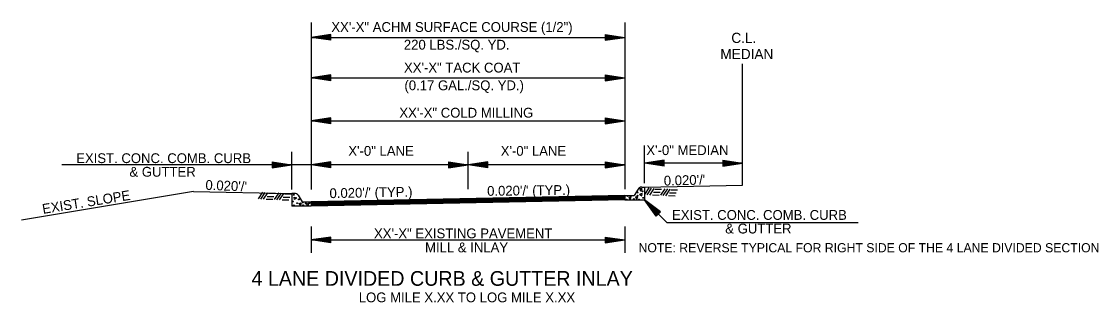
# Model space of a CAD drawing. Extents: x 544199 to 1930787, y -1968972 to 596640.
# Drawn here: x 551627 to 552451, y -1966339 to -1966124 of the extents above; entities that cross this region are included whole.
import ezdxf

# ---------------------------------------------------------------- set-up
doc = ezdxf.new("R2010")
doc.units = 0
doc.layers.add('R_Border Prem', color=7, linetype='Continuous')
doc.layers.add('R_Draft', color=7, linetype='Continuous')

msp = doc.modelspace()

# ---------------------------------------------------------------- linework, layer by layer
at = {"layer": 'R_Draft'}
for p, q in [((551848.34, -1966125.12), (551848.34, -1966252.54)), ((551863.34, -1966134.13), (551848.34, -1966136.38)), ((551848.34, -1966136.38), (552088.27, -1966136.38)), ((551863.34, -1966138.63), (551848.34, -1966136.38)), ((551863.34, -1966134.5), (551850.84, -1966136.38)), ((551863.34, -1966138.25), (551850.84, -1966136.38)), ((551863.34, -1966134.89), (551853.42, -1966136.38)), ((551863.34, -1966137.87), (551853.42, -1966136.38)), ((551863.34, -1966135.26), (551855.92, -1966136.38)), ((551863.34, -1966137.5), (551855.92, -1966136.38)), ((551863.34, -1966135.64), (551858.46, -1966136.38)), ((551863.34, -1966137.11), (551858.46, -1966136.38)), ((551863.34, -1966136.03), (551860.97, -1966136.38)), ((551863.34, -1966136.73), (551860.97, -1966136.38)), ((551863.34, -1966138.63), (551863.34, -1966134.13)), ((552073.27, -1966134.13), (552088.27, -1966136.38)), ((552073.27, -1966134.13), (552073.27, -1966138.63)), ((552073.27, -1966134.5), (552085.76, -1966136.38)), ((552073.27, -1966134.89), (552083.18, -1966136.38)), ((552073.27, -1966135.26), (552080.68, -1966136.38)), ((552073.27, -1966135.65), (552078.14, -1966136.38)), ((552073.27, -1966136.03), (552075.64, -1966136.38)), ((552073.27, -1966138.63), (552088.27, -1966136.38)), ((552073.27, -1966137.11), (552078.14, -1966136.38)), ((552073.27, -1966137.87), (552083.18, -1966136.38)), ((552073.27, -1966138.25), (552085.76, -1966136.38)), ((552073.27, -1966137.5), (552080.68, -1966136.38)), ((552073.27, -1966136.73), (552075.64, -1966136.38)), ((552178.29, -1966249.37), (552178.29, -1966156.59)), ((551863.34, -1966165), (551848.34, -1966167.25)), ((551848.34, -1966167.25), (552088.27, -1966167.25)), ((551863.34, -1966169.5), (551848.34, -1966167.25)), ((551863.34, -1966165.37), (551850.84, -1966167.25)), ((551863.34, -1966169.12), (551850.84, -1966167.25)), ((551863.34, -1966165.76), (551853.42, -1966167.25)), ((551863.34, -1966168.74), (551853.42, -1966167.25)), ((551863.34, -1966166.13), (551855.92, -1966167.25)), ((551863.34, -1966168.37), (551855.92, -1966167.25)), ((551863.34, -1966166.51), (551858.46, -1966167.25)), ((551863.34, -1966167.98), (551858.46, -1966167.25)), ((551863.34, -1966166.9), (551860.97, -1966167.25)), ((551863.34, -1966167.6), (551860.97, -1966167.25)), ((551863.34, -1966169.5), (551863.34, -1966165)), ((552073.27, -1966165), (552088.27, -1966167.25)), ((552073.27, -1966165), (552073.27, -1966169.5)), ((552073.27, -1966165.37), (552085.76, -1966167.25)), ((552073.27, -1966165.76), (552083.18, -1966167.25)), ((552073.27, -1966166.13), (552080.68, -1966167.25)), ((552073.27, -1966166.52), (552078.14, -1966167.25)), ((552073.27, -1966166.9), (552075.64, -1966167.25)), ((552073.27, -1966169.5), (552088.27, -1966167.25)), ((552073.27, -1966167.98), (552078.14, -1966167.25)), ((552073.27, -1966168.74), (552083.18, -1966167.25)), ((552073.27, -1966169.12), (552085.76, -1966167.25)), ((552073.27, -1966168.37), (552080.68, -1966167.25)), ((552073.27, -1966167.6), (552075.64, -1966167.25)), ((551863.34, -1966197.93), (551848.34, -1966200.18)), ((551848.34, -1966200.18), (552088.27, -1966200.18)), ((551863.34, -1966202.43), (551848.34, -1966200.18)), ((551863.34, -1966198.3), (551850.84, -1966200.18)), ((551863.34, -1966202.05), (551850.84, -1966200.18)), ((551863.34, -1966198.68), (551853.42, -1966200.18)), ((551863.34, -1966201.67), (551853.42, -1966200.18)), ((551863.34, -1966199.06), (551855.92, -1966200.18)), ((551863.34, -1966201.29), (551855.92, -1966200.18)), ((551863.34, -1966199.44), (551858.46, -1966200.18)), ((551863.34, -1966200.9), (551858.46, -1966200.18)), ((551863.34, -1966199.82), (551860.97, -1966200.18)), ((551863.34, -1966200.53), (551860.97, -1966200.18)), ((551863.34, -1966202.43), (551863.34, -1966197.93)), ((552073.27, -1966197.93), (552088.27, -1966200.18)), ((552073.27, -1966197.93), (552073.27, -1966202.43)), ((552073.27, -1966198.3), (552085.76, -1966200.18)), ((552073.27, -1966198.68), (552083.18, -1966200.18)), ((552073.27, -1966199.06), (552080.68, -1966200.18)), ((552073.27, -1966199.45), (552078.14, -1966200.18)), ((552073.27, -1966199.82), (552075.64, -1966200.18)), ((552073.27, -1966202.43), (552088.27, -1966200.18)), ((552073.27, -1966200.91), (552078.14, -1966200.18)), ((552073.27, -1966201.67), (552083.18, -1966200.18)), ((552073.27, -1966202.05), (552085.76, -1966200.18)), ((552073.27, -1966201.29), (552080.68, -1966200.18)), ((552073.27, -1966200.53), (552075.64, -1966200.18)), ((552103.27, -1966247.75), (552103.27, -1966219.02)), ((551833.34, -1966252.54), (551833.34, -1966223.82)), ((551968.34, -1966252.37), (551968.34, -1966223.82)), ((551848.34, -1966233.71), (551657.53, -1966233.71)), ((551818.33, -1966231.46), (551833.33, -1966233.71)), ((551818.33, -1966231.46), (551818.33, -1966235.96)), ((551818.33, -1966231.84), (551830.83, -1966233.71)), ((551818.33, -1966232.22), (551828.25, -1966233.71)), ((551818.33, -1966232.6), (551825.75, -1966233.71)), ((551818.33, -1966232.99), (551823.21, -1966233.71)), ((551818.33, -1966233.36), (551820.7, -1966233.71)), ((551818.33, -1966235.96), (551833.33, -1966233.71)), ((551818.33, -1966234.45), (551823.21, -1966233.71)), ((551818.33, -1966235.21), (551828.25, -1966233.71)), ((551818.33, -1966235.59), (551830.83, -1966233.71)), ((551818.33, -1966234.83), (551825.75, -1966233.71)), ((551818.33, -1966234.07), (551820.7, -1966233.71)), ((551863.34, -1966231.46), (551848.34, -1966233.71)), ((551968.34, -1966233.71), (551848.34, -1966233.71)), ((551863.34, -1966235.96), (551848.34, -1966233.71)), ((551863.34, -1966231.84), (551850.84, -1966233.71)), ((551863.34, -1966235.59), (551850.84, -1966233.71)), ((551863.34, -1966232.22), (551853.42, -1966233.71)), ((551863.34, -1966235.21), (551853.42, -1966233.71)), ((551863.34, -1966232.6), (551855.92, -1966233.71)), ((551863.34, -1966234.83), (551855.92, -1966233.71)), ((551863.34, -1966232.98), (551858.46, -1966233.71)), ((551863.34, -1966234.44), (551858.46, -1966233.71)), ((551863.34, -1966233.36), (551860.97, -1966233.71)), ((551863.34, -1966234.07), (551860.97, -1966233.71)), ((551863.34, -1966235.96), (551863.34, -1966231.46)), ((551953.34, -1966231.46), (551968.34, -1966233.71)), ((551953.34, -1966231.46), (551953.34, -1966235.96)), ((551953.34, -1966231.84), (551965.83, -1966233.71)), ((551953.34, -1966232.22), (551963.25, -1966233.71)), ((551953.34, -1966232.6), (551960.76, -1966233.71)), ((551953.34, -1966232.99), (551958.21, -1966233.71)), ((551953.34, -1966233.36), (551955.71, -1966233.71)), ((551953.34, -1966235.96), (551968.34, -1966233.71)), ((551953.34, -1966234.45), (551958.21, -1966233.71)), ((551953.34, -1966235.21), (551963.25, -1966233.71)), ((551953.34, -1966235.59), (551965.83, -1966233.71)), ((551953.34, -1966234.83), (551960.76, -1966233.71)), ((551953.34, -1966234.07), (551955.71, -1966233.71)), ((551983.34, -1966231.46), (551968.34, -1966233.71)), ((552088.27, -1966233.71), (551968.34, -1966233.71)), ((551983.34, -1966235.96), (551968.34, -1966233.71)), ((551983.34, -1966231.84), (551970.84, -1966233.71)), ((551983.34, -1966235.59), (551970.84, -1966233.71)), ((551983.34, -1966232.22), (551973.42, -1966233.71)), ((551983.34, -1966235.21), (551973.42, -1966233.71)), ((551983.34, -1966232.6), (551975.92, -1966233.71)), ((551983.34, -1966234.83), (551975.92, -1966233.71)), ((551983.34, -1966232.98), (551978.46, -1966233.71)), ((551983.34, -1966234.44), (551978.46, -1966233.71)), ((551983.34, -1966233.36), (551980.97, -1966233.71)), ((551983.34, -1966234.07), (551980.97, -1966233.71)), ((551983.34, -1966235.96), (551983.34, -1966231.46)), ((552073.27, -1966231.46), (552088.27, -1966233.71)), ((552073.27, -1966231.46), (552073.27, -1966235.96)), ((552073.27, -1966231.84), (552085.76, -1966233.71)), ((552073.27, -1966232.22), (552083.18, -1966233.71)), ((552073.27, -1966232.6), (552080.68, -1966233.71)), ((552073.27, -1966232.99), (552078.14, -1966233.71)), ((552073.27, -1966233.36), (552075.64, -1966233.71)), ((552073.27, -1966235.96), (552088.27, -1966233.71)), ((552073.27, -1966234.45), (552078.14, -1966233.71)), ((552073.27, -1966235.21), (552083.18, -1966233.71)), ((552073.27, -1966235.59), (552085.76, -1966233.71)), ((552073.27, -1966234.83), (552080.68, -1966233.71)), ((552073.27, -1966234.07), (552075.64, -1966233.71)), ((552118.29, -1966230.23), (552103.29, -1966232.48)), ((552118.29, -1966234.73), (552103.29, -1966232.48)), ((552178.29, -1966232.48), (552103.29, -1966232.48)), ((552118.29, -1966230.61), (552105.8, -1966232.48)), ((552118.29, -1966234.36), (552105.8, -1966232.48)), ((552118.29, -1966230.99), (552108.38, -1966232.48)), ((552118.29, -1966233.97), (552108.38, -1966232.48)), ((552118.29, -1966231.36), (552110.88, -1966232.48)), ((552118.29, -1966233.6), (552110.88, -1966232.48)), ((552118.29, -1966231.75), (552113.42, -1966232.48)), ((552118.29, -1966233.21), (552113.42, -1966232.48)), ((552118.29, -1966232.13), (552115.92, -1966232.48)), ((552118.29, -1966232.83), (552115.92, -1966232.48)), ((552118.29, -1966234.73), (552118.29, -1966230.23)), ((552163.29, -1966230.23), (552178.29, -1966232.48)), ((552163.29, -1966230.23), (552163.29, -1966234.73)), ((552163.29, -1966230.61), (552175.79, -1966232.48)), ((552163.29, -1966230.99), (552173.21, -1966232.48)), ((552163.29, -1966231.36), (552170.71, -1966232.48)), ((552163.29, -1966231.75), (552168.17, -1966232.48)), ((552163.29, -1966232.13), (552165.66, -1966232.48)), ((552163.29, -1966234.73), (552178.29, -1966232.48)), ((552163.29, -1966233.22), (552168.17, -1966232.48)), ((552163.29, -1966233.97), (552173.21, -1966232.48)), ((552163.29, -1966234.36), (552175.79, -1966232.48)), ((552163.29, -1966233.6), (552170.71, -1966232.48)), ((552163.29, -1966232.83), (552165.66, -1966232.48)), ((552098.31, -1966252.33), (552095.28, -1966257.13)), ((552101.13, -1966250.83), (552103.29, -1966250.87)), ((552103.29, -1966250.87), (552178.29, -1966249.37)), ((552103.29, -1966250.87), (552103.29, -1966260.62)), ((552103.57, -1966256.44), (552106.94, -1966251.43)), ((552105.36, -1966256.65), (552108.74, -1966251.64)), ((552107.36, -1966256.86), (552110.74, -1966251.85)), ((552111.24, -1966252.22), (552116.33, -1966252.26)), ((552115.83, -1966256.98), (552119.21, -1966251.97)), ((552117.62, -1966257.19), (552121, -1966252.18)), ((552119.63, -1966257.4), (552123, -1966252.39)), ((552123.51, -1966252.77), (552128.59, -1966252.81)), ((551758.34, -1966254.07), (551626.66, -1966276.02)), ((551758.34, -1966254.07), (551833.34, -1966255.57)), ((551808, -1966259.66), (551811.37, -1966254.65)), ((551809.79, -1966259.87), (551813.17, -1966254.86)), ((551811.79, -1966260.08), (551815.17, -1966255.07)), ((551813.79, -1966260), (551818.88, -1966260.04)), ((551814.67, -1966257.87), (551819.76, -1966257.91)), ((551815.67, -1966255.45), (551820.76, -1966255.49)), ((551820.26, -1966260.21), (551823.64, -1966255.2)), ((551822.05, -1966260.41), (551825.43, -1966255.41)), ((551824.06, -1966260.62), (551827.43, -1966255.61)), ((551826.06, -1966260.54), (551831.15, -1966260.58)), ((551826.93, -1966258.41), (551832.02, -1966258.45)), ((551827.93, -1966255.99), (551833.02, -1966256.03)), ((551835.51, -1966255.53), (551833.34, -1966255.57)), ((551833.34, -1966255.57), (551833.34, -1966265.42)), ((551838.32, -1966257.03), (551841.42, -1966261.93)), ((552088.27, -1966257.13), (551848.34, -1966261.93)), ((552088.27, -1966257.43), (551848.34, -1966262.23)), ((552088.27, -1966257.73), (551848.34, -1966262.53)), ((552088.27, -1966258.03), (551848.34, -1966262.83)), ((552088.27, -1966258.33), (551848.34, -1966263.13)), ((552088.27, -1966258.63), (551848.34, -1966263.43)), ((552088.27, -1966258.93), (551848.34, -1966263.73)), ((552088.27, -1966259.23), (551848.34, -1966264.03)), ((552088.27, -1966259.53), (551848.34, -1966264.33)), ((552088.27, -1966259.83), (551848.34, -1966264.63)), ((552088.27, -1966260.13), (551848.34, -1966264.93)), ((552088.27, -1966260.43), (551848.34, -1966265.23)), ((552088.27, -1966260.62), (551848.34, -1966265.42)), ((552088.27, -1966257.13), (552095.28, -1966257.13)), ((552088.27, -1966257.13), (552088.27, -1966260.62)), ((552088.27, -1966260.62), (552103.29, -1966260.62)), ((552103.29, -1966260.62), (552120.26, -1966277.85)), ((552112.22, -1966272.89), (552103.29, -1966260.62)), ((552115.42, -1966269.73), (552103.29, -1966260.62)), ((552109.36, -1966256.77), (552114.45, -1966256.81)), ((552110.24, -1966254.64), (552115.33, -1966254.68)), ((552121.63, -1966257.31), (552126.72, -1966257.36)), ((552122.5, -1966255.19), (552127.59, -1966255.23)), ((551848.34, -1966265.42), (551833.34, -1966265.42)), ((551841.42, -1966261.93), (551848.34, -1966261.93)), ((551848.34, -1966261.93), (551848.34, -1966265.42)), ((552112.48, -1966272.62), (552105.05, -1966262.41)), ((552115.16, -1966269.99), (552105.05, -1966262.41)), ((552114.88, -1966270.26), (552106.86, -1966264.24)), ((552112.76, -1966272.36), (552106.86, -1966264.24)), ((552113.02, -1966272.09), (552108.62, -1966266.02)), ((552114.62, -1966270.52), (552108.62, -1966266.02)), ((552114.34, -1966270.79), (552110.4, -1966267.84)), ((552113.3, -1966271.82), (552110.4, -1966267.84)), ((552114.07, -1966271.06), (552112.16, -1966269.62)), ((552113.57, -1966271.56), (552112.16, -1966269.62)), ((552112.22, -1966272.89), (552115.42, -1966269.73)), ((552120.26, -1966277.85), (552266.74, -1966277.85)), ((551848.34, -1966280.93), (551848.34, -1966300.93)), ((552088.27, -1966280.93), (552088.27, -1966300.93)), ((551863.34, -1966288.93), (551848.34, -1966291.18)), ((551848.34, -1966291.18), (552088.27, -1966291.18)), ((551863.34, -1966293.43), (551848.34, -1966291.18)), ((551863.34, -1966289.3), (551850.84, -1966291.18)), ((551863.34, -1966293.05), (551850.84, -1966291.18)), ((551863.34, -1966289.69), (551853.42, -1966291.18)), ((551863.34, -1966292.67), (551853.42, -1966291.18)), ((551863.34, -1966290.06), (551855.92, -1966291.18)), ((551863.34, -1966292.3), (551855.92, -1966291.18)), ((551863.34, -1966290.44), (551858.46, -1966291.18)), ((551863.34, -1966291.91), (551858.46, -1966291.18)), ((551863.34, -1966290.83), (551860.97, -1966291.18)), ((551863.34, -1966291.53), (551860.97, -1966291.18)), ((551863.34, -1966293.43), (551863.34, -1966288.93)), ((552073.27, -1966288.93), (552088.27, -1966291.18)), ((552073.27, -1966288.93), (552073.27, -1966293.43)), ((552073.27, -1966289.3), (552085.76, -1966291.18)), ((552073.27, -1966289.69), (552083.18, -1966291.18)), ((552073.27, -1966290.06), (552080.68, -1966291.18)), ((552073.27, -1966290.45), (552078.14, -1966291.18)), ((552073.27, -1966290.83), (552075.64, -1966291.18)), ((552073.27, -1966293.43), (552088.27, -1966291.18)), ((552073.27, -1966291.91), (552078.14, -1966291.18)), ((552073.27, -1966292.67), (552083.18, -1966291.18)), ((552073.27, -1966293.05), (552085.76, -1966291.18)), ((552073.27, -1966292.3), (552080.68, -1966291.18)), ((552073.27, -1966291.53), (552075.64, -1966291.18))]:
    msp.add_line(p, q, dxfattribs=at)
for points in [[(552088.27, -1966125.12), (552088.27, -1966252.37)], [(552100.3, -1966253.98), (552101.43, -1966252.19), (552099.66, -1966251.83), (552100.3, -1966253.72)], [(551837.28, -1966258.99), (551835.52, -1966260.13), (551835.14, -1966258.35), (551837.05, -1966258.99)], [(552091.99, -1966260.59), (552093.12, -1966258.8), (552091.35, -1966258.44), (552091.99, -1966260.33)], [(552097.12, -1966260.35), (552098.25, -1966258.57), (552096.48, -1966258.2), (552097.12, -1966260.09)], [(552099.35, -1966256.22), (552101.11, -1966257.36), (552101.49, -1966255.58), (552099.58, -1966256.22)], [(551840.09, -1966264.97), (551838.96, -1966263.18), (551840.72, -1966262.81), (551840.09, -1966264.71)], [(551845.75, -1966265.29), (551844.61, -1966263.51), (551846.39, -1966263.14), (551845.75, -1966265.03)]]:
    msp.add_lwpolyline(points, dxfattribs=at)
for centre in [(551834.27, -1966261.73), (551834.9, -1966256.7), (551838.82, -1966260.14), (552089.64, -1966260.3), (552090.28, -1966257.56), (552092.47, -1966257.97), (552095.11, -1966259.86), (552097.81, -1966257.37), (552097.98, -1966254.8), (552099.07, -1966260.23), (552101.73, -1966253.93), (552102.36, -1966258.96), (551835.09, -1966264.71), (551837.56, -1966263), (551841.75, -1966262.47), (551842.16, -1966264.63), (551844.06, -1966263.25), (551846.99, -1966263.07)]:
    msp.add_circle(centre, 0.339, dxfattribs=at)
for centre, start, end in [((552101.07, -1966254.08), 88.88036, 147.72436), ((551835.56, -1966258.79), 32.27564, 91.11964)]:
    msp.add_arc(centre, 3.26, start, end, dxfattribs=at)

# ---------------------------------------------------------------- texts
at = {"layer": 'R_Border Prem'}
msp.add_text('NOTE: REVERSE TYPICAL FOR RIGHT SIDE OF THE 4 LANE DIVIDED SECTION', height=7, dxfattribs=at).set_placement((552098.71, -1966300.59))
at = {"layer": 'R_Draft'}
for s, height, p in [('XX\'-X" ACHM SURFACE COURSE (1/2")', 7.5, (551863.68, -1966132.21)), ('220 LBS./SQ. YD. ', 7.5, (551919.17, -1966145.75)), ('C.L.', 7.8, (552169.71, -1966140.67)), ('MEDIAN', 7.8, (552161.3, -1966153.03)), ('XX\'-X" TACK COAT', 7.5, (551919.26, -1966163.23)), ('(0.17 GAL./SQ. YD.)', 7.5, (551919.61, -1966176.77)), ('XX\'-X" COLD MILLING', 7.5, (551915.72, -1966197.69)), ('X\'-0" LANE', 7.5, (551876.68, -1966226.85)), ('X\'-0" LANE', 7.5, (551993.27, -1966226.85)), ('X\'-0" MEDIAN', 7.5, (552104.68, -1966226.3)), ('EXIST. CONC. COMB. CURB', 7.5, (551668.5, -1966232.43)), ('& GUTTER ', 7.5, (551709.22, -1966242.83)), ('EXIST. CONC. COMB. CURB', 7.5, (552124.34, -1966275.79)), ('XX\'-X" EXISTING PAVEMENT', 7.5, (551896.32, -1966289.86)), ('& GUTTER ', 7.5, (552165.06, -1966286.19)), ('MILL & INLAY', 7.5, (551935.39, -1966300.58)), ('4 LANE DIVIDED CURB & GUTTER INLAY', 11.25, (551802.61, -1966326.17)), ('LOG MILE X.XX TO LOG MILE X.XX', 7.5, (551884.67, -1966338.77))]:
    msp.add_text(s, height=height, dxfattribs=at).set_placement(p)
for s, rotation, p in [("0.020'/'", 1.55034, (552118.14, -1966249.66)), ('EXIST. SLOPE', 9.15344, (551643.15, -1966271.27)), ("0.020'/'", 357.78305, (551767.24, -1966252.82)), ("0.020'/' (TYP.)", 1.09843, (551862.35, -1966259.23)), ("0.020'/' (TYP.)", 0.73873, (551982.92, -1966257.46))]:
    msp.add_text(s, height=7.5, rotation=rotation, dxfattribs=at).set_placement(p)

doc.saveas('drawing.dxf')
